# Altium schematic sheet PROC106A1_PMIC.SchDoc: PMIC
size 431 x 279 mm; Date: Not shown in title block; ApprovedBy: Not shown in title block; CheckedBy: Not shown in title block; Author: Not shown in title block; CompanyName: Not shown in title block; DrawnBy: Antony/Anand Ram; Engineer: Not shown in title block; Organization: Not shown in title block; Address1: Not shown in title block; Address2: Not shown in title block; Address3: Not shown in title block; Address4: Not shown in title block; DocumentNumber: 5; Revision: Use project parameter SCH_Rev; SheetNumber: 5; SheetTotal: 12; PageSetup: Record=PageOptions¦CenterHorizontal=True¦CenterVertical=True¦PrintScale=1.00¦XCorrection=1.00¦YCorrection=1.00¦PrintKind=0¦BorderSize=5000000¦LeftOffset=0¦BottomOffset=0¦Orientation=2¦PaperLength=1000¦PaperWidth=1000¦Scale=100¦PaperSource=15¦PrintQuality=600¦MediaType=1¦DitherType=10¦PaperKind=Letter¦PrintScaleMode=1
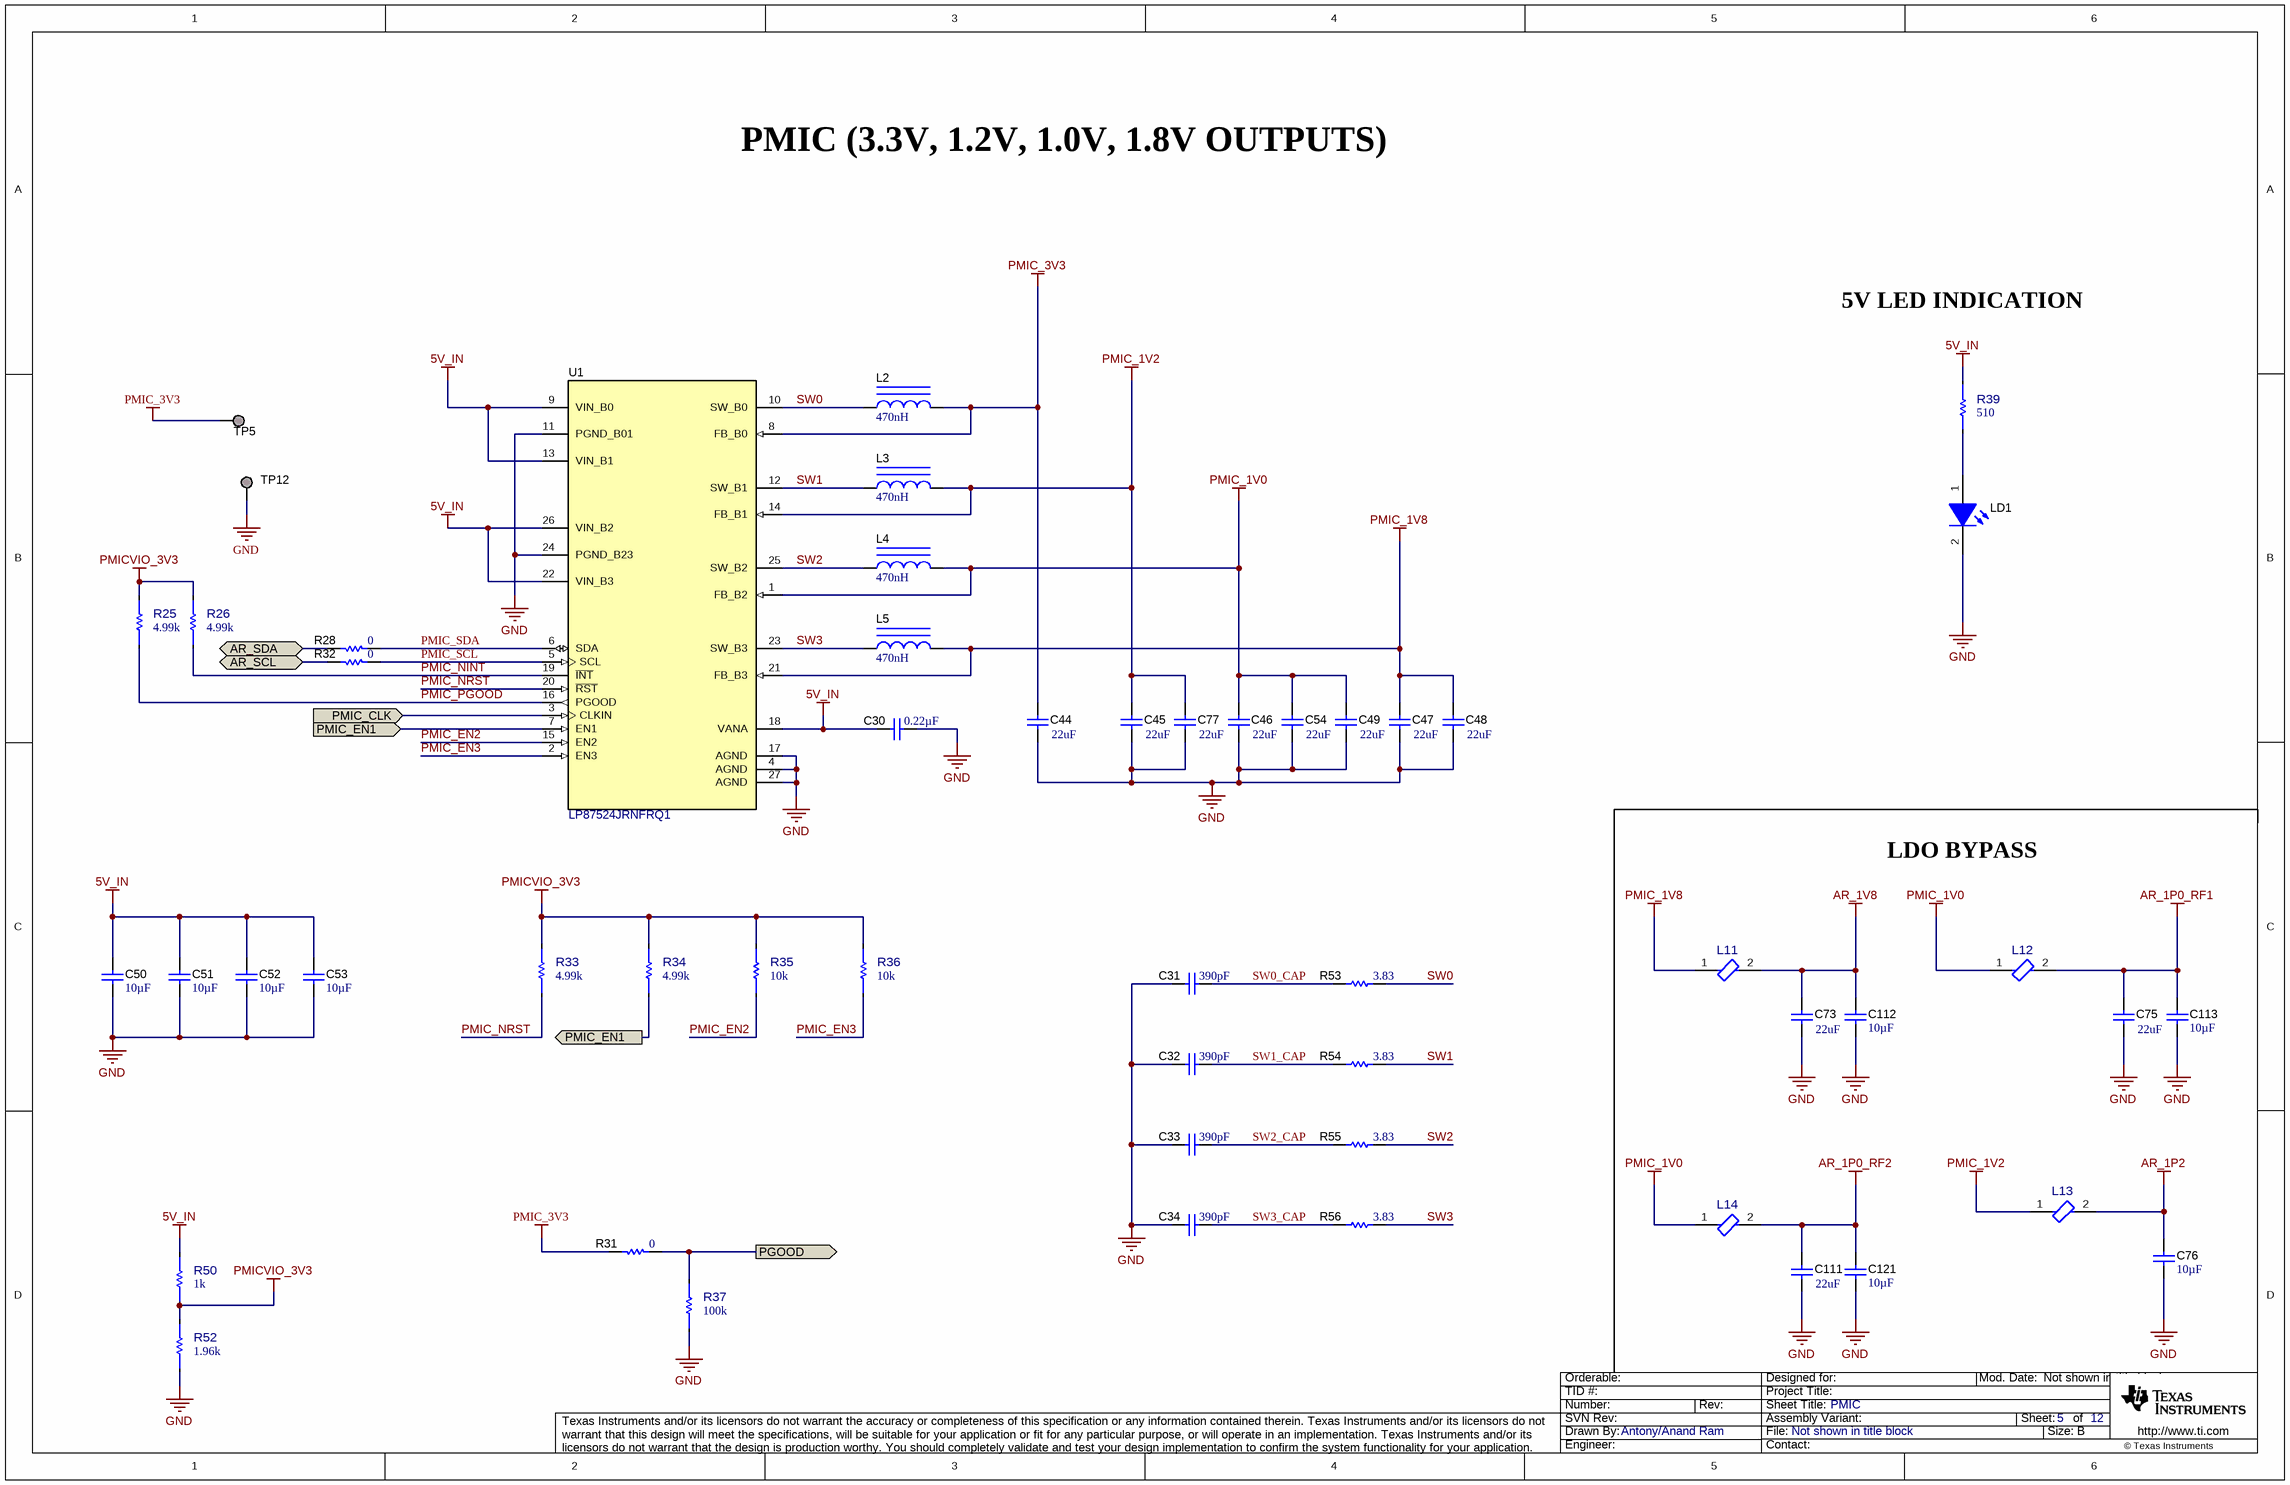
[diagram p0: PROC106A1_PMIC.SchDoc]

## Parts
C30  ValueDisplayed: 0.22µF  [0402L]  (hidden comment: GCM155R71C224KE02D)
C31  ValueDisplayed: 390pF  [0402L]  (hidden comment: CGA2B2C0G1H391J050BA)
C32  ValueDisplayed: 390pF  [0402L]  (hidden comment: CGA2B2C0G1H391J050BA)
C33  ValueDisplayed: 390pF  [0402L]  (hidden comment: CGA2B2C0G1H391J050BA)
C34  ValueDisplayed: 390pF  [0402L]  (hidden comment: CGA2B2C0G1H391J050BA)
C44  ValueDisplayed: 22uF  [1206_180L]  (hidden comment: GCM31CR71A226KE02L)
C45  ValueDisplayed: 22uF  [1206_180L]  (hidden comment: GCM31CR71A226KE02L)
C46  ValueDisplayed: 22uF  [1206_180L]  (hidden comment: GCM31CR71A226KE02L)
C47  ValueDisplayed: 22uF  [1206_180L]  (hidden comment: GCM31CR71A226KE02L)
C48  ValueDisplayed: 22uF  [1206_180L]  (hidden comment: GCM31CR71A226KE02L)
C49  ValueDisplayed: 22uF  [1206_180L]  (hidden comment: GCM31CR71A226KE02L)
C50  Cap_F: 10µF  [0805_HV1]  (hidden comment: GCM21BR71A106KE22L)
C51  Cap_F: 10µF  [0805_HV1]  (hidden comment: GCM21BR71A106KE22L)
C52  Cap_F: 10µF  [0805_HV1]  (hidden comment: GCM21BR71A106KE22L)
C53  Cap_F: 10µF  [0805_HV1]  (hidden comment: GCM21BR71A106KE22L)
C54  ValueDisplayed: 22uF  [1206_180L]  (hidden comment: GCM31CR71A226KE02L)
C73  ValueDisplayed: 22uF  [1206_180L]  (hidden comment: GCM31CR71A226KE02L)
C75  ValueDisplayed: 22uF  [1206_180L]  (hidden comment: GCM31CR71A226KE02L)
C76  Cap_F: 10µF  [0805L]  (hidden comment: GCM21BR71A106KE22L)
C77  ValueDisplayed: 22uF  [1206_180L]  (hidden comment: GCM31CR71A226KE02L)
C111  ValueDisplayed: 22uF  [1206_180L]  (hidden comment: GCM31CR71A226KE02L)
C112  Cap_F: 10µF  [0805L]  (hidden comment: GCM21BR71A106KE22L)
C113  Cap_F: 10µF  [0805L]  (hidden comment: GCM21BR71A106KE22L)
C121  Cap_F: 10µF  [0805L]  (hidden comment: GCM21BR71A106KE22L)
L2  ValueDisplayed: 470nH  [DFE252012P]  (hidden comment: DFE252012PD-R47M)
L3  ValueDisplayed: 470nH  [DFE252012P]  (hidden comment: DFE252012PD-R47M)
L4  ValueDisplayed: 470nH  [DFE252012P]  (hidden comment: DFE252012PD-R47M)
L5  ValueDisplayed: 470nH  [DFE252012P]  (hidden comment: DFE252012PD-R47M)
L11  MPZ2012S101ATD25  [FP-MPZ2012S101ATD25_0805-MFG]  (value not drawn)
L12  MPZ2012S101ATD25  [FP-MPZ2012S101ATD25_0805-MFG]  (value not drawn)
L13  MPZ2012S101ATD25  [FP-MPZ2012S101ATD25_0805-MFG]  (value not drawn)
L14  MPZ2012S101ATD25  [FP-MPZ2012S101ATD25_0805-MFG]  (value not drawn)
LD1  APHHS1005CGCK  [APHHS1005_Green]  (value not drawn)
R25  value 4.99k  [FP-ERJ-1GNF4991C_0201-IPC_C]  (hidden comment: ERJ-1GNF4991C)
R26  value 4.99k  [FP-ERJ-1GNF4991C_0201-IPC_C]  (hidden comment: ERJ-1GNF4991C)
R28  ValueDisplayed: 0  [0201L]  (hidden comment: ERJ-1GN0R00C)
R31  ValueDisplayed: 0  [0201L]  (hidden comment: ERJ-1GN0R00C)
R32  ValueDisplayed: 0  [0201L]  (hidden comment: ERJ-1GN0R00C)
R33  value 4.99k  [FP-ERJ-1GNF4991C_0201-IPC_C]  (hidden comment: ERJ-1GNF4991C)
R34  value 4.99k  [FP-ERJ-1GNF4991C_0201-IPC_C]  (hidden comment: ERJ-1GNF4991C)
R35  value 10k  [FP-ERA-1AEB103C_0201-IPC_C]  (hidden comment: ERA-1AEB103C)
R36  value 10k  [FP-ERA-1AEB103C_0201-IPC_C]  (hidden comment: ERA-1AEB103C)
R37  value 100k  [FP-ERJ-1GNF1003C_0201-IPC_C]  (hidden comment: ERJ-1GNF1003C)
R39  value 510  [FP-ERJ-1GNJ511C_0201-IPC_C]  (hidden comment: ERJ-1GNJ511C)
R50  value 1k  [FP-ERJ-1GNJ102C_0201-IPC_C]  (hidden comment: ERJ-1GNJ102C)
R52  value 1.96k  [FP-ERJ-1GNF1961C_0201-IPC_C]  (hidden comment: ERJ-1GNF1961C)
R53  ValueDisplayed: 3.83  [0402L]  (hidden comment: CRCW04023R83FKED)
R54  ValueDisplayed: 3.83  [0402L]  (hidden comment: CRCW04023R83FKED)
R55  ValueDisplayed: 3.83  [0402L]  (hidden comment: CRCW04023R83FKED)
R56  ValueDisplayed: 3.83  [0402L]  (hidden comment: CRCW04023R83FKED)
TP5  TESTPOINT  [TP_25MIL-SMT]  (value not drawn)  (no BOM)
TP12  TESTPOINT  [TP_VIA_060RND040]  (value not drawn)  (no BOM)
U1  LP87524JRNFRQ1  [RNF0026C]

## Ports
AR_SCL (bidir), AR_SDA (bidir), PGOOD (out), PMIC_CLK (in), PMIC_EN1 (in), PMIC_EN1 (out)

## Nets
5V_IN: C30.1 C50.1 C51.1 C52.1 C53.1 R39.1 R50.2 U1.9(VIN_B0) U1.13(VIN_B1) U1.18(VANA) U1.22(VIN_B3) U1.26(VIN_B2)
AR_1P0_RF1: C75.2 C113.1 L12.2
AR_1P0_RF2: C111.2 C121.1 L14.2
AR_1P2: C76.1 L13.2
AR_1V8: C73.2 C112.1 L11.2
GND: C30.2 C31.2 C32.2 C33.1 C34.1 C44.1 C45.1 C46.1 C47.1 C48.1 C49.1 C50.2 C51.2 C52.2 C53.2 C54.1 C73.1 C75.1 C76.2 C77.1 C111.1 C112.2 C113.2 C121.2 LD1.2(K) R37.1 R52.1 TP12.1 U1.4(AGND) U1.11(PGND_B01) U1.17(AGND) U1.24(PGND_B23) U1.27(AGND)
PMIC_1V0: C46.2 C49.2 C54.2 L4.1 L12.1 L14.1 U1.1(FB_B2)
PMIC_1V2: C45.2 C77.2 L3.1 L13.1 U1.14(FB_B1)
PMIC_1V8: C47.2 C48.2 L5.1 L11.1 U1.21(FB_B3)
PMIC_3V3: C44.2 L2.1 R31.1 TP5.1 U1.8(FB_B0)
PMICVIO_3V3: R25.2 R26.2 R33.2 R34.2 R35.2 R36.2 R50.1 R52.2
AR_SCL: R32.1 ; port AR_SCL
AR_SDA: R28.1 ; port AR_SDA
PGOOD: R31.2 R37.2 ; port PGOOD
PMIC_CLK: U1.3(CLKIN) ; port PMIC_CLK
PMIC_EN1: R34.1 U1.7(EN1) ; port PMIC_EN1
PMIC_EN2: R35.1 U1.15(EN2)
PMIC_EN3: R36.1 U1.2(EN3)
PMIC_NINT: R26.1 U1.19(~{INT})
PMIC_NRST: R33.1 U1.20(~{RST})
PMIC_PGOOD: R25.1 U1.16(PGOOD)
PMIC_SCL: R32.2 U1.5(SCL)
PMIC_SDA: R28.2 U1.6(SDA)
SW0: L2.2 R53.2 U1.10(SW_B0)
SW0_CAP: C31.1 R53.1
SW1: L3.2 R54.2 U1.12(SW_B1)
SW1_CAP: C32.1 R54.1
SW2: L4.2 R55.2 U1.25(SW_B2)
SW2_CAP: C33.2 R55.1
SW3: L5.2 R56.2 U1.23(SW_B3)
SW3_CAP: C34.2 R56.1
NetLD1_1: LD1.1(A) R39.2

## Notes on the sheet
- PMIC (3.3V, 1.2V, 1.0V, 1.8V OUTPUTS)
- 5V LED INDICATION
- LDO BYPASS

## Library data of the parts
C30 = CMP-0078265-1: CAP, CERM, 0.22 µF, 16 V,+/- 10%, X7R, AEC-Q200 Grade 1, 0402; Manufacturer: MuRata; Value: 0.22uF; AEC Category: Q200; AEC Grade: 1; AEC Qualified: Y; Cap_Case: 0402; Cap_F: 220nF; Polarized: N; SizeArea_mm2: 0.5; SizeAreaWB_mm2: 3; SizeZ_mm: 0.6; TaMax_C: 125°C; TaMin_C: -55°C; U/M: EA; Value2: 16V
C31-C34 = CMP-0085511-1: CAP, CERM, 390 pF, 50 V,+/- 5%, C0G/NP0, AEC-Q200 Grade 1, 0402; Manufacturer: TDK; AEC Qualified: Y; SizeZ_mm: 0.6; VDC_V: 50V; AEC Category: Q200; AEC Grade: 1; Cap_Case: 0402; Polarized: N; SizeArea_mm2: 0.5; SizeAreaWB_mm2: 3; TaMax_C: 125°C; TaMin_C: -55°C; U/M: EA; Value: 390pF
C44-C47 = CMP-0008811-3: CAP, CERM, 22 uF, 10 V, +/- 10%, X7R, AEC-Q200 Grade 1, 1206; Manufacturer: MuRata; AEC Qualified: Y; Cap_F: 22µF; SizeZ_mm: 1.8; VDC_V: 10V; AEC Category: Q200; AEC Grade: 1; Cap_Case: 1206; Polarized: N; SizeArea_mm2: 5.12; SizeAreaWB_mm2: 10.92; SizeX_mm: 3.2; SizeY_mm: 1.6; TaMax_C: 125°C; TaMin_C: -55°C; U/M: EA; Value1: Unknown; Value: 22uF
C48 C49 C54 C73 C75 C77 C111 = CMP-0008811-3: CAP, CERM, 22 uF, 10 V, +/- 10%, X7R, AEC-Q200 Grade 1, 1206; Manufacturer: MuRata; Cap_F: 22µF; AEC Qualified: Y; SizeZ_mm: 1.8; VDC_V: 10V; AEC Category: Q200; AEC Grade: 1; Cap_Case: 1206; Polarized: N; SizeArea_mm2: 5.12; SizeAreaWB_mm2: 10.92; SizeX_mm: 3.2; SizeY_mm: 1.6; TaMax_C: 125°C; TaMin_C: -55°C; U/M: EA; Value1: Unknown; Value: 22uF
C50-C53 C76 C112 C113 C121 = CMP-0008017-2: CAP, CERM, 10 uF, 10 V, +/- 10%, X7R, 0805; Manufacturer: MuRata; Value: 10uF; AEC Category: Q200; Cap_Case: 0805; Polarized: N; SizeArea_mm2: 2.5; SizeAreaWB_mm2: 6.75; SizeX_mm: 2; SizeY_mm: 1.25; SizeZ_mm: 1.45; TaMax_C: 125°C; TaMin_C: -55°C; U/M: EA; Value1: Unknown; Value2: 10V
L2-L5 = CMP-0058944-1: Inductor, Shielded, 470 nH, 4.7 A, 0.021 ohm, SMD; Manufacturer: MuRata Toko; DCR_ohm: 0.021; Irms: 4.7A @ 40C rise; Isat: 6.1A @ 30% inductance drop; SizeZ_mm: 1.2; AEC Category: Q200; Imax_A: 4.7A; SizeArea_mm2: 5; SizeAreaWB_mm2: 10.5; SizeX_mm: 2.5; SizeY_mm: 2; Value: 470nH
L11-L14 = CMP-0089947-1: 100 Ohms @ 100MHz 1 Power Line Ferrite Bead 0805 (2012 Metric) 4A 20mOhm; Manufacturer: TDK; DCR_ohm: 0.02; SizeZ_mm: 1.05mm; AEC Grade: Grade 1; AEC Qualified: Yes; Impedance At Frequency: 100Ω @ 100MHz; Tolerance_%: 25%
LD1 = CMP-0067682-2: LED, Green, SMD; Manufacturer: Kingbright; Angle: 120.0; Power_TotalModule: 75mW; SizeZ_mm: 0.6; Vf_V: 2.1V; Vr_V: 5V; Io_A: 20mA; Ir_A: 10µA; SizeArea_mm2: 0.5; SizeAreaWB_mm2: 3.0; SizeX_mm: 1.0; Tjmax_C: 85°C; Value1: 0.075W
R25 R26 R33 R34 = CMP-0090497-1: 4.99 kOhms ±1% 0.05W, 1/20W Chip Resistor 0201 (0603 Metric) Automotive AEC-Q200 Thick Film; Manufacturer: Panasonic Electronic Components; AEC Grade: Grade 1; AEC Qualified: Yes; Power_W: 50mW; SizeZ_mm: 0.26mm; TempCo: 200ppm/°C; VDC_V: 25V
R28 R31 R32 = CMP-0065361-1: RES, 0, 5%, .05 W, AEC-Q200 Grade 0, 0201; Manufacturer: Panasonic; AEC Qualified: Y; Power_W: 50mW; SizeZ_mm: 0.26; TempCo: ppm/C; AEC Category: Q200; EIA_Code: E24; Green_Lifecycle: Not Set; Green_REACh: Incomplete; SizeArea_mm2: 0.18; SizeX_mm: 0.6; SizeY_mm: 0.3; U/M: EA; Value2: .05W; Value: 0; Value_Code: 0000
R35 R36 = CMP-0090084-1: RES SMD 10K OHM 0.1% 1/20W 0201; Manufacturer: Panasonic; AEC Qualified: No; Power_W: 50mW; SizeZ_mm: 0.26mm; TempCo: 25ppm/°C; VDC_V: 25V
R37 = CMP-0090298-1: 100 kOhms ±1% 0.05W, 1/20W Chip Resistor 0201 (0603 Metric) Automotive AEC-Q200 Thick Film; Manufacturer: Panasonic Electronic Components; AEC Grade: Grade 1; AEC Qualified: Yes; Power_W: 50mW; SizeZ_mm: 0.26mm; TempCo: 200ppm/°C; VDC_V: 25V
R39 = CMP-0090502-1: 510 Ohms ±5% 0.05W, 1/20W Chip Resistor 0201 (0603 Metric) Automotive AEC-Q200 Thick Film; Manufacturer: Panasonic Electronic Components; AEC Grade: Grade 1; AEC Qualified: Yes; Power_W: 50mW; SizeZ_mm: 0.26mm; TempCo: 200ppm/°C; VDC_V: 25V
R50 = CMP-0090500-1: 1 kOhms ±5% 0.05W, 1/20W Chip Resistor 0201 (0603 Metric) Automotive AEC-Q200 Thick Film; Manufacturer: Panasonic Electronic Components; AEC Grade: Grade 1; AEC Qualified: Yes; Power_W: 50mW; SizeZ_mm: 0.26mm; TempCo: 200ppm/°C; VDC_V: 25V
R52 = CMP-0090496-1: Res Thick Film 0201 1.96K Ohm 1% 1/20W 200ppm/C Molded SMD T/R; Manufacturer: Panasonic; AEC Grade: Grade 1; AEC Qualified: Yes; Power_W: 50mW; SizeZ_mm: 0.26mm; TempCo: 200ppm/°C; VDC_V: 25V
R53-R56 = CMP-0026363-2: RES, 3.83, 1%, 0.063 W, AEC-Q200 Grade 0, 0402; Manufacturer: Vishay-Dale; TempCo: 100 ppm/C; AEC Qualified: Y; Power_W: 63mW; VDC_V: 50V; SizeZ_mm: 0.6; AEC Category: Q200; AEC Grade: 0; EIA_Code: E96; SizeArea_mm2: 0.5; SizeX_mm: 1; Value2: 0.063W; Value: 3.83; Value_Code: 3R83
TP5 TP12 = CMP-0078143-3: TEST POINT.  No entry in BOM.
U1 = CMP-0079120-2: 4-A + 2.5-A + Two 1.5-A Buck Converters With Integrated Switches, RNF0026C (VQFN-HR-26); Alternate PartNumber: LP87524JRNFTQ1; Alternate Manufacturer: Texas Instruments; SizeAreaWB_mm2: 27.5; SizeZ_mm: 0.9; SizeX_mm: 4; SizeY_mm: 4.5; SizeArea_mm2: 18; CompType: IC; AEC Qualified: Y; AEC Category: Q200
